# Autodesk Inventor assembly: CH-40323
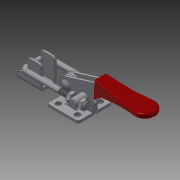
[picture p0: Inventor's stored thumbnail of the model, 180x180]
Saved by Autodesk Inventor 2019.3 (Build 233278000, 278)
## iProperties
Company: ·L?¤¤?
Created: 2010-06
Part Number: CH-40323
Material: Ogólny
Description: STEP AP203
Document SubType Name: Assembly
Designer: CADENGINEERING4
Stock Number: DOCISK ZACZEPOWY KABŁĄKOWY
Sending System: SolidWorks 2005179
Preprocessor: SwSTEP 2.0
Title: CH-40323.STEP
Author: ·L?¥Î?
Revision Number: ANY
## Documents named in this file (9)
- D:\Vault_2016\Projekty\Clamptek\STRONA\Latch type clamp\CH-40323\CH-40323.iam
- D:\Vault_2016\Projekty\Clamptek\STRONA\Latch type clamp\CH-40323\M4___.ipt
- D:\Vault_2016\Projekty\Clamptek\STRONA\Latch type clamp\CH-40323\04___.ipt
- D:\Vault_2016\Projekty\Clamptek\STRONA\Latch type clamp\CH-40323\06___.ipt
- D:\Vault_2016\Projekty\Clamptek\STRONA\Latch type clamp\CH-40323\M4_______.ipt
- D:\Vault_2016\Projekty\Clamptek\STRONA\Latch type clamp\CH-40323\02___.ipt
- D:\Vault_2016\Projekty\Clamptek\STRONA\Latch type clamp\CH-40323\05___.ipt
- D:\Vault_2016\Projekty\Clamptek\STRONA\Latch type clamp\CH-40323\00___.iam
- D:\Vault_2016\Projekty\Clamptek\STRONA\Latch type clamp\CH-40323\01___.ipt
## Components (10 placed, 10 different names)
1. M4_??_1 — Zestawiające:13, Zestawiające:14
2. 04_??_2 — Równoległe:1, Zestawiające:3, Równoległe:3
3. 06_??_3 — Zestawiające:8, Zestawiające:9
4. M4????_??_4 — Zestawiające:12, Zestawiające:15
5. M4_??_5 — Zestawiające:10, Zestawiające:17
6. 02_??_6 — Zestawiające:3, Zestawiające:5, Zestawiające:6, Zestawiające:7, Zestawiające:10, Zestawiające:11, Zestawiające:12, Zestawiające:13
7. 05_??_7 — Zestawiające:4, Równoległe:2, Kątowe:1, Zestawiające:5, Zestawiające:6, Zestawiające:7, Zestawiające:14, Zestawiające:15, Zestawiające:16, Zestawiające:17
8. M4????_??_8 — Zestawiające:11, Zestawiające:16
9. 00_??_9 [sub-assembly] — Zestawiające:1, Zestawiające:2, Zestawiające:4, Równoległe:2, Zestawiające:8, Zestawiające:9, Równoległe:3
10. 01_??_10 — Zestawiające:1, Zestawiające:2, Równoległe:1, Kątowe:1
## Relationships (21: Mate 17, Flush 3, Angle 1)
- Zestawiające:1 [Mate]: 00_??_9 ↔ 01_??_10
- Zestawiające:2 [Mate]: 00_??_9 ↔ 01_??_10
- Równoległe:1 [Flush]: 04_??_2 ↔ 01_??_10
- Zestawiające:3 [Mate]: 04_??_2 ↔ 02_??_6
- Zestawiające:4 [Mate]: 05_??_7 ↔ 00_??_9
- Równoległe:2 [Flush]: 05_??_7 ↔ 00_??_9
- Kątowe:1 [Angle]: 05_??_7 ↔ 01_??_10
- Zestawiające:5 [Mate]: 02_??_6 ↔ 05_??_7
- Zestawiające:6 [Mate]: 02_??_6 ↔ 05_??_7
- Zestawiające:7 [Mate]: 02_??_6 ↔ 05_??_7
- Zestawiające:8 [Mate]: 06_??_3 ↔ 00_??_9
- Zestawiające:9 [Mate]: 06_??_3 ↔ 00_??_9
- Równoległe:3 [Flush]: 04_??_2 ↔ 00_??_9
- Zestawiające:10 [Mate]: M4_??_5 ↔ 02_??_6
- Zestawiające:11 [Mate]: 02_??_6 ↔ M4????_??_8
- Zestawiające:12 [Mate]: M4????_??_4 ↔ 02_??_6
- Zestawiające:13 [Mate]: M4_??_1 ↔ 02_??_6
- Zestawiające:14 [Mate]: M4_??_1 ↔ 05_??_7
- Zestawiające:15 [Mate]: M4????_??_4 ↔ 05_??_7
- Zestawiające:16 [Mate]: 05_??_7 ↔ M4????_??_8
- Zestawiające:17 [Mate]: M4_??_5 ↔ 05_??_7
